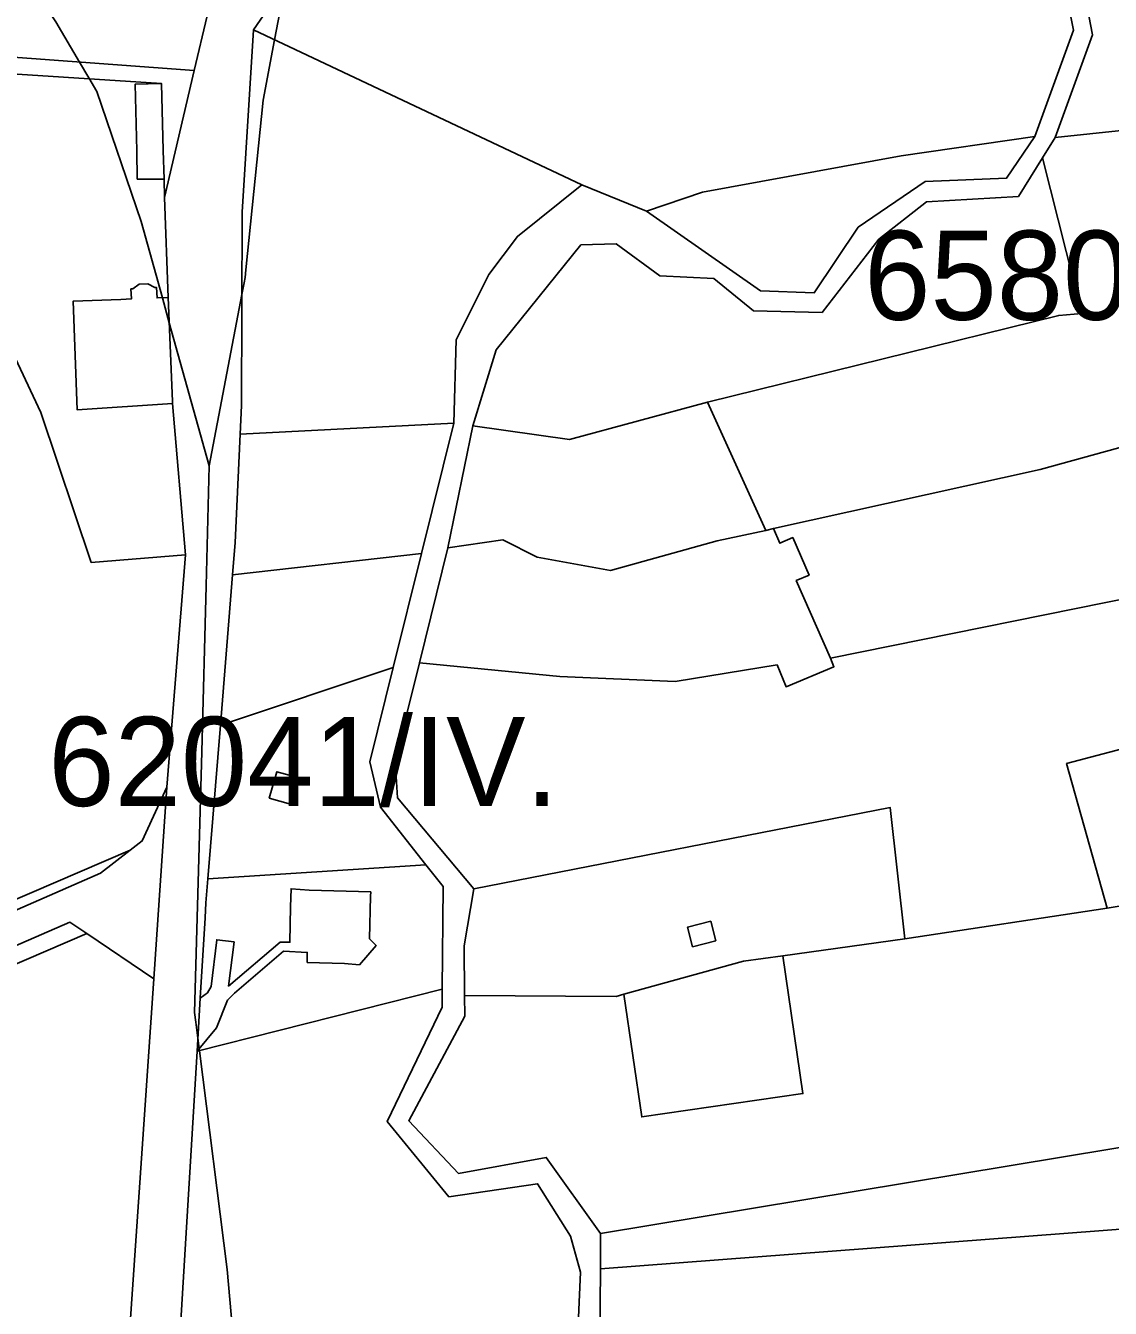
# Model space of a CAD drawing. Extents: x -522079 to -518792, y -1142400 to -1139961.
# Drawn here: x -520623.1 to -520440.6, y -1141173.1 to -1140957.2 of the extents above; entities that cross this region are included whole.
import ezdxf

# ---------------------------------------------------------------- set-up
doc = ezdxf.new("R2010")
doc.units = 0
for name, color, linetype in [('Hranice parcel', 7, 'Continuous'), ('Poz předměty', 7, 'Continuous'), ('Vnitřní kresba', 7, 'Continuous'), ('Značky bodu BP', 7, 'Continuous'), ('Značky budov', 7, 'Continuous'), ('Značky kultur', 7, 'Continuous')]:
    doc.layers.add(name, color=color, linetype=linetype)

msp = doc.modelspace()

# ---------------------------------------------------------------- linework, layer by layer
at = {"layer": 'Hranice parcel'}
for points in [[(-520562.58, -1140925.73), (-520584.75, -1140957.97), (-520586.68, -1140988.64), (-520586.76, -1141021.16), (-520586.99, -1141025.98), (-520587.85, -1141044.25), (-520588.29, -1141049.68), (-520590.32, -1141074.97), (-520592.43, -1141100.83), (-520592.76, -1141104.85), (-520592.91, -1141107.42), (-520593.72, -1141120.93), (-520594.25, -1141129.86), (-520597.46, -1141183.55)], [(-520606.07, -1141183.78), (-520601.54, -1141117.64), (-520599.33, -1141085.41), (-520596.21, -1141046.3), (-520598.37, -1141020.83), (-520598.4, -1141020.44), (-520599.09, -1141003), (-520599.73, -1140986.18), (-520594.75, -1140964.79), (-520590.36, -1140946.34)], [(-521027.41, -1141281.92), (-520897.83, -1141225.78), (-520885.55, -1141220.5), (-520708.05, -1141142.54), (-520688.68, -1141134.03), (-520675.02, -1141128.07), (-520610.52, -1141099.9), (-520605.48, -1141096), (-520603.47, -1141094.45), (-520599.33, -1141085.41), (-520601.54, -1141117.64), (-520612.8, -1141110.04), (-520615.64, -1141108.13), (-520683.34, -1141137.56), (-520705.75, -1141147.3), (-520882.39, -1141224.1), (-520895.38, -1141229.74), (-521025.25, -1141286.2)]]:
    msp.add_lwpolyline(points, dxfattribs=at)
for points in [[(-520443.57, -1140958.81), (-520446.27, -1140944.76), (-520440.46, -1140948.61), (-520424.71, -1140946.66), (-520422.88, -1140952.85), (-520417.34, -1140971.6), (-520424.88, -1140973.41), (-520431.3, -1140974.09), (-520449.86, -1140976.07)], [(-520604.41, -1140978.31), (-520604.67, -1140967.12), (-520600.24, -1140966.98), (-520599.94, -1140978.24), (-520599.81, -1140983.06), (-520604.3, -1140983.07)], [(-520402.73, -1140992.69), (-520415.87, -1140997.65), (-520426.91, -1140999.86), (-520442.37, -1141005.47), (-520445.36, -1141005.71), (-520451.99, -1140979.48), (-520449.86, -1140976.07), (-520431.3, -1140974.09), (-520424.88, -1140973.41), (-520420.75, -1140990.63), (-520419.75, -1140994.8), (-520408.08, -1140992), (-520411.18, -1140979.06), (-520413.21, -1140970.61), (-520409.61, -1140969.39), (-520406.94, -1140968.49), (-520405.49, -1140974.52), (-520405.06, -1140976.3), (-520400.22, -1140975.02), (-520400.73, -1140973.02), (-520399.62, -1140972.67), (-520397.64, -1140983.14), (-520398.66, -1140983.49), (-520405.04, -1140985.68)], [(-520453.28, -1140975.93), (-520458.05, -1140982.9), (-520471.76, -1140983.46), (-520483.03, -1140991.17), (-520490.41, -1141002.21), (-520499.42, -1141001.88), (-520518.62, -1140988.49), (-520509.19, -1140985.26), (-520475.75, -1140979.18)], [(-520614.42, -1141021.92), (-520615.08, -1141003.61), (-520607.09, -1141003.32), (-520605.29, -1141003.25), (-520605.37, -1141001.56), (-520605.04, -1141001.54), (-520603.99, -1141000.76), (-520602.52, -1141000.7), (-520601.36, -1141001.34), (-520601.06, -1141001.34), (-520600.97, -1141003.07), (-520599.09, -1141003), (-520598.4, -1141020.44), (-520598.37, -1141020.83)], [(-520582.09, -1141087.24), (-520580.82, -1141082.81), (-520577.31, -1141083.78), (-520578.55, -1141088.26)], [(-520676.95, -1141126.77), (-520605.48, -1141096), (-520610.52, -1141099.9), (-520675.02, -1141128.07)], [(-520565.25, -1141110.92), (-520564.14, -1141112.07), (-520566.93, -1141115.3), (-520569.44, -1141115.09), (-520575.71, -1141114.91), (-520575.7, -1141113.22), (-520579.73, -1141112.98), (-520587.97, -1141120.05), (-520589.1, -1141121.25), (-520590.98, -1141125.93), (-520594.25, -1141129.86), (-520593.72, -1141120.93), (-520592.5, -1141120.04), (-520591.88, -1141118.95), (-520590.95, -1141111.08), (-520588.02, -1141111.45), (-520588.95, -1141118.89), (-520580.29, -1141111.47), (-520578.63, -1141111.5), (-520578.5, -1141105.52), (-520578.44, -1141102.51), (-520575.39, -1141102.74), (-520565.03, -1141103.04), (-520565.05, -1141103.74)], [(-520615.64, -1141108.13), (-520612.8, -1141110.04), (-520677.78, -1141138.02), (-520683.09, -1141140.3), (-520683.34, -1141137.56)], [(-520510.88, -1141112.27), (-520511.72, -1141108.95), (-520507.81, -1141107.97), (-520506.98, -1141111.26)]]:
    msp.add_lwpolyline(points, close=True, dxfattribs=at)
at = {"layer": 'Poz předměty'}
for points in [[(-520679.92, -1141124.76), (-520699.09, -1140943.92), (-520632.04, -1140920.85), (-520634.37, -1140902.81), (-520641.23, -1140863.72), (-520646.19, -1140843.58), (-520650.7, -1140826.31), (-520634.79, -1140817.77), (-520621.9, -1140866.86), (-520618.56, -1140880.81), (-520614.37, -1140907.34), (-520612.5, -1140933.48), (-520590.36, -1140946.34), (-520594.75, -1140964.79), (-520649.51, -1140960.76), (-520648.03, -1140963.9), (-520620.51, -1141022.34), (-520612.04, -1141047.58), (-520596.21, -1141046.3), (-520599.33, -1141085.41), (-520603.47, -1141094.45), (-520605.48, -1141096), (-520676.95, -1141126.77)], [(-520586.99, -1141025.98), (-520551.07, -1141024.16), (-520556.5, -1141046.1), (-520588.29, -1141049.68), (-520587.85, -1141044.25)], [(-520565.18, -1141081.15), (-520563.4, -1141088.78), (-520555.74, -1141098.46), (-520592.43, -1141100.83), (-520590.32, -1141074.97), (-520561.24, -1141065.24)], [(-520582.09, -1141087.24), (-520578.55, -1141088.26), (-520577.31, -1141083.78), (-520580.82, -1141082.81)], [(-520597.46, -1141183.55), (-520594.25, -1141129.86), (-520552.98, -1141119.42), (-520553, -1141122.43), (-520562.26, -1141141.67), (-520551.87, -1141154.33), (-520536.94, -1141152.14), (-520531.44, -1141160.96), (-520529.73, -1141167.05), (-520530.26, -1141178.39), (-520534.49, -1141178.34), (-520588.63, -1141182.42)], [(-520432.59, -1141179.7), (-520440.68, -1141181.04), (-520523.78, -1141178.47), (-520526.48, -1141178.44), (-520526.38, -1141166.45), (-520421.91, -1141158.52), (-520408.18, -1141157.48), (-520425.27, -1141175.41)]]:
    msp.add_lwpolyline(points, close=True, dxfattribs=at)
at = {"layer": 'Vnitřní kresba'}
for points in [[(-520530.26, -1141178.39), (-520529.73, -1141167.05), (-520531.44, -1141160.96), (-520536.94, -1141152.14), (-520551.87, -1141154.33), (-520562.26, -1141141.67), (-520553, -1141122.43), (-520552.98, -1141119.42), (-520552.84, -1141102.13), (-520555.74, -1141098.46), (-520563.4, -1141088.78), (-520565.18, -1141081.15), (-520561.24, -1141065.24), (-520556.5, -1141046.1), (-520551.07, -1141024.16), (-520550.66, -1141010.15), (-520545.15, -1140999.12), (-520540.36, -1140992.71), (-520529.52, -1140984.06), (-520518.62, -1140988.49), (-520499.42, -1141001.88), (-520490.41, -1141002.21), (-520483.03, -1140991.17), (-520471.76, -1140983.46), (-520458.05, -1140982.9), (-520453.28, -1140975.93), (-520446.79, -1140958), (-520449.47, -1140944.32)], [(-520446.27, -1140944.76), (-520443.57, -1140958.81), (-520449.86, -1140976.07), (-520451.99, -1140979.48), (-520456.05, -1140986), (-520471.51, -1140986.91), (-520479.55, -1140993.19), (-520489.07, -1141005.5), (-520500.6, -1141005.26), (-520507.31, -1140999.82), (-520516.37, -1140999.34), (-520523.73, -1140993.96), (-520529.65, -1140994.14), (-520543.9, -1141011.82), (-520547.82, -1141024.57), (-520552.06, -1141045.13), (-520556.84, -1141064.48), (-520560.89, -1141080.93), (-520560.53, -1141087.18), (-520547.68, -1141102.49), (-520549.29, -1141112.12), (-520549.23, -1141120.44), (-520549.21, -1141123.97), (-520558.62, -1141141.55), (-520550.27, -1141150.4), (-520535.5, -1141147.72), (-520526.34, -1141160.53), (-520526.38, -1141166.45), (-520526.48, -1141178.44)]]:
    msp.add_lwpolyline(points, dxfattribs=at)
at = {"layer": 'Značky bodu BP'}
for points in [[(-520627.56, -1140949.7), (-520621.19, -1140951.83), (-520619.9, -1140953.77), (-520618, -1140956.63), (-520614.03, -1140963.37), (-520612.45, -1140966.05), (-520611.1, -1140968.35), (-520603.66, -1140990.19), (-520600.09, -1141003.03), (-520598.92, -1141007.25), (-520592.23, -1141031.31), (-520592.74, -1141051.53), (-520593.45, -1141079.44), (-520594.66, -1141123.3), (-520594.45, -1141124.94), (-520594.12, -1141127.62), (-520593.85, -1141129.76), (-520589.2, -1141166.56), (-520587.79, -1141182.35)], [(-520579.44, -1140950.25), (-520581.21, -1140959.64), (-520583.12, -1140969.77), (-520586.03, -1140998.35), (-520586.16, -1140999.62), (-520586.33, -1141000.54), (-520586.71, -1141002.52), (-520592.23, -1141031.31), (-520598.92, -1141007.25), (-520600.09, -1141003.03), (-520603.66, -1140990.19), (-520611.1, -1140968.35), (-520612.45, -1140966.05), (-520614.03, -1140963.37), (-520618, -1140956.63)], [(-520587.79, -1141182.35), (-520589.2, -1141166.56), (-520593.85, -1141129.76), (-520594.12, -1141127.62), (-520594.45, -1141124.94), (-520594.66, -1141123.3), (-520593.45, -1141079.44), (-520592.74, -1141051.53), (-520592.23, -1141031.31), (-520586.71, -1141002.52), (-520586.33, -1141000.54), (-520586.16, -1140999.62), (-520586.03, -1140998.35), (-520583.12, -1140969.77), (-520581.21, -1140959.64), (-520579.44, -1140950.25)]]:
    msp.add_lwpolyline(points, dxfattribs=at)
at = {"layer": 'Značky budov'}
msp.add_lwpolyline([(-520607.02, -1141187.64), (-520665.65, -1141273.94), (-520677.78, -1141138.02), (-520612.8, -1141110.04), (-520601.54, -1141117.64), (-520606.07, -1141183.78)], close=True, dxfattribs=at)
at = {"layer": 'Značky kultur'}
for points in [[(-520529.52, -1140984.06), (-520584.75, -1140957.97), (-520562.58, -1140925.73), (-520536.98, -1140945.57), (-520524.57, -1140946.3), (-520449.47, -1140944.32), (-520446.79, -1140958), (-520453.28, -1140975.93), (-520475.75, -1140979.18), (-520509.19, -1140985.26), (-520518.62, -1140988.49)], [(-520586.68, -1140988.64), (-520584.75, -1140957.97), (-520529.52, -1140984.06), (-520540.36, -1140992.71), (-520545.15, -1140999.12), (-520550.66, -1141010.15), (-520551.07, -1141024.16), (-520586.99, -1141025.98), (-520586.76, -1141021.16)], [(-520649.51, -1140960.76), (-520594.75, -1140964.79), (-520599.73, -1140986.18), (-520599.81, -1140983.06), (-520599.94, -1140978.24), (-520600.24, -1140966.98), (-520648.03, -1140963.9)], [(-520620.51, -1141022.34), (-520648.03, -1140963.9), (-520600.24, -1140966.98), (-520604.67, -1140967.12), (-520604.41, -1140978.31), (-520604.3, -1140983.07), (-520599.81, -1140983.06), (-520599.73, -1140986.18), (-520599.09, -1141003), (-520600.97, -1141003.07), (-520601.06, -1141001.34), (-520601.36, -1141001.34), (-520602.52, -1141000.7), (-520603.99, -1141000.76), (-520605.04, -1141001.54), (-520605.37, -1141001.56), (-520605.29, -1141003.25), (-520607.09, -1141003.32), (-520615.08, -1141003.61), (-520614.42, -1141021.92), (-520598.37, -1141020.83), (-520596.21, -1141046.3), (-520612.04, -1141047.58)], [(-520456.05, -1140986), (-520451.99, -1140979.48), (-520445.36, -1141005.71), (-520449.27, -1141006.02), (-520508.38, -1141020.64), (-520531.57, -1141026.89), (-520547.82, -1141024.57), (-520543.9, -1141011.82), (-520529.65, -1140994.14), (-520523.73, -1140993.96), (-520516.37, -1140999.34), (-520507.31, -1140999.82), (-520500.6, -1141005.26), (-520489.07, -1141005.5), (-520479.55, -1140993.19), (-520471.51, -1140986.91)], [(-520400.21, -1141032.13), (-520399.24, -1141042.3), (-520408.06, -1141046.45), (-520431.05, -1141052.26), (-520487.67, -1141063.72), (-520493.42, -1141050.65), (-520491.27, -1141049.7), (-520494.03, -1141043.4), (-520496.2, -1141044.35), (-520497.24, -1141041.88), (-520452.37, -1141031.92), (-520412.3, -1141020.92), (-520402.65, -1141017.41), (-520392.22, -1141014.66), (-520391.74, -1141015.46), (-520389.08, -1141019.93), (-520401.32, -1141023.68), (-520401.95, -1141022.11), (-520410.31, -1141025.45), (-520406.62, -1141034.69)], [(-520552.06, -1141045.13), (-520547.82, -1141024.57), (-520531.57, -1141026.89), (-520508.38, -1141020.64), (-520498.56, -1141042.19), (-520506.76, -1141043.95), (-520524.68, -1141048.94), (-520537, -1141046.7), (-520542.8, -1141043.78)], [(-520487.08, -1141065.15), (-520495.15, -1141068.52), (-520496.65, -1141064.79), (-520513.82, -1141067.62), (-520533.21, -1141066.79), (-520556.84, -1141064.48), (-520552.06, -1141045.13), (-520542.8, -1141043.78), (-520537, -1141046.7), (-520524.68, -1141048.94), (-520506.76, -1141043.95), (-520498.56, -1141042.19), (-520497.24, -1141041.88), (-520496.2, -1141044.35), (-520494.03, -1141043.4), (-520491.27, -1141049.7), (-520493.42, -1141050.65), (-520487.67, -1141063.72)], [(-520561.24, -1141065.24), (-520590.32, -1141074.97), (-520588.29, -1141049.68), (-520556.5, -1141046.1)], [(-520487.67, -1141063.72), (-520431.05, -1141052.26), (-520425.4, -1141075.5), (-520447.94, -1141081.43), (-520441.13, -1141105.78), (-520475.18, -1141110.92), (-520477.6, -1141088.85), (-520547.68, -1141102.49), (-520560.53, -1141087.18), (-520560.89, -1141080.93), (-520556.84, -1141064.48), (-520533.21, -1141066.79), (-520513.82, -1141067.62), (-520496.65, -1141064.79), (-520495.15, -1141068.52), (-520487.08, -1141065.15)], [(-520375.66, -1141093.7), (-520394.23, -1141097.85), (-520441.13, -1141105.78), (-520447.94, -1141081.43), (-520425.4, -1141075.5), (-520390.79, -1141066.51), (-520384.48, -1141082.4), (-520371.97, -1141078.27), (-520365.3, -1141073.88), (-520360.71, -1141085.77), (-520364.98, -1141088.31), (-520364.74, -1141089.55), (-520366.94, -1141090.81), (-520374.62, -1141093.47)], [(-520495.67, -1141113.78), (-520502.3, -1141114.71), (-520522.42, -1141120.25), (-520523.74, -1141120.61), (-520549.23, -1141120.44), (-520549.29, -1141112.12), (-520547.68, -1141102.49), (-520477.6, -1141088.85), (-520475.18, -1141110.92)], [(-520492.31, -1141136.96), (-520495.67, -1141113.78), (-520475.18, -1141110.92), (-520441.13, -1141105.78), (-520394.23, -1141097.85), (-520375.66, -1141093.7), (-520374.68, -1141099.98), (-520397.79, -1141103.97), (-520395.09, -1141114.42), (-520393.3, -1141121.36), (-520387.46, -1141120.02), (-520397.97, -1141139.24), (-520423.06, -1141143.4), (-520526.34, -1141160.53), (-520535.5, -1141147.72), (-520550.27, -1141150.4), (-520558.62, -1141141.55), (-520549.21, -1141123.97), (-520549.23, -1141120.44), (-520523.74, -1141120.61), (-520522.42, -1141120.25), (-520519.42, -1141140.9)], [(-520552.84, -1141102.13), (-520552.98, -1141119.42), (-520594.25, -1141129.86), (-520590.98, -1141125.93), (-520589.1, -1141121.25), (-520587.97, -1141120.05), (-520579.73, -1141112.98), (-520575.7, -1141113.22), (-520575.71, -1141114.91), (-520569.44, -1141115.09), (-520566.93, -1141115.3), (-520564.14, -1141112.07), (-520565.25, -1141110.92), (-520565.05, -1141103.74), (-520565.03, -1141103.04), (-520575.39, -1141102.74), (-520578.44, -1141102.51), (-520578.5, -1141105.52), (-520578.63, -1141111.5), (-520580.29, -1141111.47), (-520588.95, -1141118.89), (-520588.02, -1141111.45), (-520590.95, -1141111.08), (-520591.88, -1141118.95), (-520592.5, -1141120.04), (-520593.72, -1141120.93), (-520592.91, -1141107.42), (-520592.76, -1141104.85), (-520592.43, -1141100.83), (-520555.74, -1141098.46)], [(-520506.98, -1141111.26), (-520507.81, -1141107.97), (-520511.72, -1141108.95), (-520510.88, -1141112.27)], [(-520522.42, -1141120.25), (-520502.3, -1141114.71), (-520495.67, -1141113.78), (-520492.31, -1141136.96), (-520519.42, -1141140.9)], [(-520526.38, -1141166.45), (-520526.34, -1141160.53), (-520423.06, -1141143.4), (-520421.91, -1141158.52)]]:
    msp.add_lwpolyline(points, close=True, dxfattribs=at)
for points in [[(-520402.73, -1140992.69), (-520415.87, -1140997.65), (-520426.91, -1140999.86), (-520442.37, -1141005.47), (-520445.36, -1141005.71)], [(-520445.36, -1141005.71), (-520449.27, -1141006.02), (-520508.38, -1141020.64)], [(-520497.24, -1141041.88), (-520452.37, -1141031.92), (-520412.3, -1141020.92), (-520402.65, -1141017.41), (-520392.22, -1141014.66)], [(-520508.38, -1141020.64), (-520498.56, -1141042.19)], [(-520498.56, -1141042.19), (-520497.24, -1141041.88)]]:
    msp.add_lwpolyline(points, dxfattribs=at)

# ---------------------------------------------------------------- texts
at = {"layer": 'Značky bodu BP'}
for s, p in [('65800/II.', (-520482, -1141006.75)), ('62041/IV.', (-520619.28, -1141088.57))]:
    msp.add_text(s, height=15, rotation=360, dxfattribs=at).set_placement(p)

doc.saveas('drawing.dxf')
